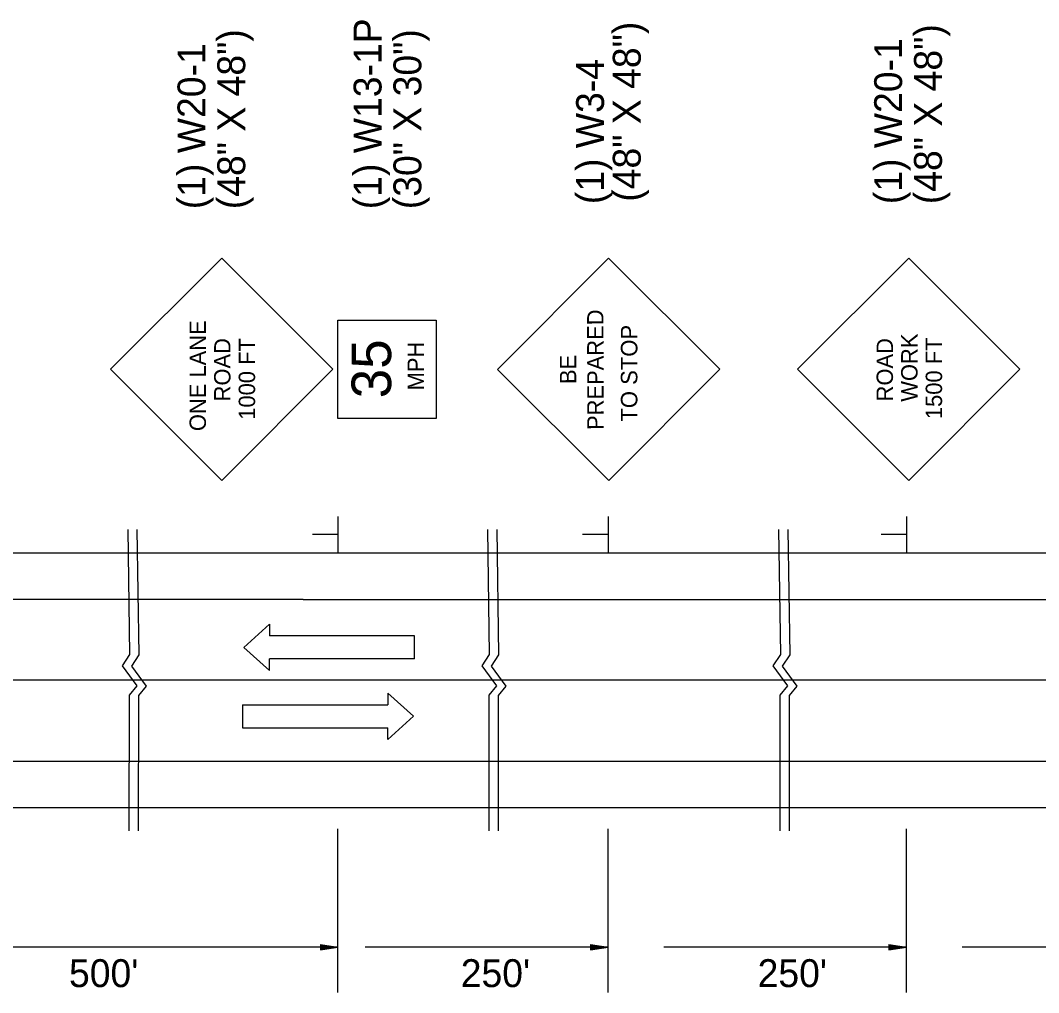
# Model space of a CAD drawing. Extents: x 1678017 to 1687792, y 404433 to 413488.
# Drawn here: x 1679003.11 to 1679025, y 409249.96 to 409270.86 of the extents above; entities that cross this region are included whole.
import ezdxf

# ---------------------------------------------------------------- set-up
doc = ezdxf.new("R2010")
doc.units = 0
doc.layers.add('Default', color=7, linetype='Continuous')
doc.layers.add('S_GRAVEL_ROAD', color=7, linetype='Continuous')

msp = doc.modelspace()

# ---------------------------------------------------------------- linework, layer by layer
at = {"layer": 'Default'}
for p, q in [((1679007.439, 409265.753), (1679005.048, 409263.362)), ((1679007.439, 409265.753), (1679009.827, 409263.362)), ((1679015.755, 409265.753), (1679013.371, 409263.358)), ((1679015.755, 409265.753), (1679018.15, 409263.367)), ((1679022.212, 409265.753), (1679019.822, 409263.362)), ((1679022.212, 409265.753), (1679024.6, 409263.362)), ((1679005.048, 409263.362), (1679007.439, 409260.972)), ((1679009.827, 409263.362), (1679007.439, 409260.972)), ((1679013.371, 409263.358), (1679015.764, 409260.972)), ((1679018.15, 409263.367), (1679015.764, 409260.972)), ((1679019.822, 409263.362), (1679022.212, 409260.972)), ((1679024.6, 409263.362), (1679022.212, 409260.972)), ((1679009.935, 409260.198), (1679009.935, 409259.416)), ((1679015.745, 409260.198), (1679015.745, 409259.416)), ((1679022.161, 409260.198), (1679022.161, 409259.416)), ((1679009.923, 409259.809), (1679009.389, 409259.809)), ((1679015.733, 409259.809), (1679015.199, 409259.809)), ((1679022.149, 409259.809), (1679021.615, 409259.809)), ((1678953.639, 409259.416), (1679044.491, 409259.416)), ((1679009.188, 409258.416), (1678996.885, 409258.416)), ((1679009.188, 409258.416), (1679044.491, 409258.416)), ((1679044.491, 409256.678), (1679000.269, 409256.678)), ((1678997.456, 409254.939), (1679009.188, 409254.939)), ((1679009.188, 409254.939), (1679044.491, 409254.939)), ((1678953.639, 409253.939), (1679044.491, 409253.939)), ((1679009.935, 409249.96), (1679009.935, 409253.481)), ((1679015.745, 409249.96), (1679015.745, 409253.481)), ((1679022.161, 409249.96), (1679022.161, 409253.481)), ((1679009.935, 409250.939), (1679000.861, 409250.939)), ((1679009.56, 409250.996), (1679009.935, 409250.939)), ((1679009.56, 409250.996), (1679009.56, 409250.883)), ((1679009.56, 409250.986), (1679009.872, 409250.939)), ((1679009.56, 409250.977), (1679009.808, 409250.939)), ((1679009.56, 409250.967), (1679009.745, 409250.939)), ((1679009.56, 409250.958), (1679009.682, 409250.939)), ((1679009.56, 409250.948), (1679009.619, 409250.939)), ((1679009.56, 409250.883), (1679009.935, 409250.939)), ((1679009.56, 409250.921), (1679009.682, 409250.939)), ((1679009.56, 409250.902), (1679009.808, 409250.939)), ((1679009.56, 409250.892), (1679009.872, 409250.939)), ((1679009.56, 409250.911), (1679009.745, 409250.939)), ((1679009.56, 409250.931), (1679009.619, 409250.939)), ((1679015.745, 409250.939), (1679010.526, 409250.939)), ((1679015.37, 409250.996), (1679015.745, 409250.939)), ((1679015.37, 409250.996), (1679015.37, 409250.883)), ((1679015.37, 409250.986), (1679015.682, 409250.939)), ((1679015.37, 409250.977), (1679015.618, 409250.939)), ((1679015.37, 409250.967), (1679015.555, 409250.939)), ((1679015.37, 409250.958), (1679015.492, 409250.939)), ((1679015.37, 409250.948), (1679015.429, 409250.939)), ((1679015.37, 409250.883), (1679015.745, 409250.939)), ((1679015.37, 409250.921), (1679015.492, 409250.939)), ((1679015.37, 409250.902), (1679015.618, 409250.939)), ((1679015.37, 409250.892), (1679015.682, 409250.939)), ((1679015.37, 409250.911), (1679015.555, 409250.939)), ((1679015.37, 409250.931), (1679015.429, 409250.939)), ((1679022.161, 409250.939), (1679016.942, 409250.939)), ((1679021.786, 409250.996), (1679022.161, 409250.939)), ((1679021.786, 409250.996), (1679021.786, 409250.883)), ((1679021.786, 409250.986), (1679022.098, 409250.939)), ((1679021.786, 409250.977), (1679022.034, 409250.939)), ((1679021.786, 409250.967), (1679021.971, 409250.939)), ((1679021.786, 409250.958), (1679021.908, 409250.939)), ((1679021.786, 409250.948), (1679021.845, 409250.939)), ((1679021.786, 409250.883), (1679022.161, 409250.939)), ((1679021.786, 409250.921), (1679021.908, 409250.939)), ((1679021.786, 409250.902), (1679022.034, 409250.939)), ((1679021.786, 409250.892), (1679022.098, 409250.939)), ((1679021.786, 409250.911), (1679021.971, 409250.939)), ((1679021.786, 409250.931), (1679021.845, 409250.939)), ((1679028.577, 409250.939), (1679023.358, 409250.939))]:
    msp.add_line(p, q, dxfattribs=at)
msp.add_lwpolyline([(1679009.934, 409262.306), (1679009.934, 409264.419), (1679012.047, 409264.419), (1679012.047, 409262.306)], close=True, dxfattribs=at)
for points in [[(1679005.417, 409259.916), (1679005.457, 409257.229), (1679005.295, 409256.987), (1679005.611, 409256.555), (1679005.445, 409256.355), (1679005.444, 409253.439)], [(1679005.616, 409259.916), (1679005.657, 409257.221), (1679005.495, 409256.979), (1679005.811, 409256.546), (1679005.645, 409256.346), (1679005.644, 409253.439)], [(1679013.151, 409259.916), (1679013.192, 409257.229), (1679013.03, 409256.987), (1679013.346, 409256.555), (1679013.18, 409256.355), (1679013.179, 409253.439)], [(1679013.351, 409259.916), (1679013.392, 409257.221), (1679013.23, 409256.979), (1679013.546, 409256.546), (1679013.379, 409256.346), (1679013.379, 409253.439)], [(1679019.411, 409259.916), (1679019.452, 409257.229), (1679019.29, 409256.987), (1679019.606, 409256.555), (1679019.439, 409256.355), (1679019.439, 409253.439)], [(1679019.611, 409259.916), (1679019.652, 409257.221), (1679019.489, 409256.979), (1679019.806, 409256.546), (1679019.639, 409256.346), (1679019.639, 409253.439)]]:
    msp.add_lwpolyline(points, dxfattribs=at)
at = {"layer": 'S_GRAVEL_ROAD'}
for p, q in [((1679007.914, 409257.384), (1679008.463, 409257.884)), ((1679008.463, 409257.884), (1679008.463, 409257.634)), ((1679011.585, 409257.634), (1679008.463, 409257.634)), ((1679011.585, 409257.134), (1679011.585, 409257.634)), ((1679008.463, 409256.884), (1679007.914, 409257.384)), ((1679011.585, 409257.134), (1679008.463, 409257.134)), ((1679008.463, 409256.884), (1679008.463, 409257.134)), ((1679011.011, 409256.401), (1679011.559, 409255.901)), ((1679011.011, 409256.401), (1679011.011, 409256.151)), ((1679007.888, 409256.151), (1679011.011, 409256.151)), ((1679007.888, 409256.151), (1679007.888, 409255.651)), ((1679011.559, 409255.901), (1679011.011, 409255.401)), ((1679007.888, 409255.651), (1679011.011, 409255.651)), ((1679011.011, 409255.401), (1679011.011, 409255.651))]:
    msp.add_line(p, q, dxfattribs=at)

# ---------------------------------------------------------------- texts
at = {"layer": 'Default'}
for s, height, rotation, p in [('(1) W13-1P', 0.6, 90, (1679010.874, 409266.804)), ('(48" X 48")', 0.6, 90, (1679007.943, 409266.804)), ('(30" X 30")', 0.6, 90, (1679011.73, 409266.804)), ('(48" X 48")', 0.6, 90, (1679016.448, 409266.965)), ('(48" X 48")', 0.6, 90, (1679022.925, 409266.912)), ('(1) W20-1', 0.6, 90, (1679022.069, 409266.912)), ('(1) W20-1', 0.6, 90, (1679007.087, 409266.804)), ('(1) W3-4', 0.6, 90, (1679015.659, 409266.912)), ('PREPARED', 0.3521, 90.1003, (1679015.651, 409262.058)), ('ONE LANE', 0.3521, 90.0004, (1679007.098, 409262.033)), ('TO STOP', 0.3544, 90.0006, (1679016.376, 409262.237)), ('ROAD', 0.352, 90, (1679007.626, 409262.672)), ('1000 FT', 0.3522, 90.0006, (1679008.155, 409262.277)), ('ROAD', 0.3521, 90.0004, (1679021.872, 409262.672)), ('WORK', 0.352, 90, (1679022.4, 409262.665)), ('1500 FT', 0.3522, 90.0006, (1679022.928, 409262.291)), ('35', 0.851, 90, (1679011.081, 409262.739)), ('MPH', 0.3522, 90.0006, (1679011.786, 409262.908)), ('BE', 0.3521, 90.1004, (1679015.062, 409263.046))]:
    msp.add_text(s, height=height, rotation=rotation, dxfattribs=at).set_placement(p)
for s, p in [("500'", (1679004.154, 409250.079)), ("250'", (1679012.578, 409250.079)), ("250'", (1679018.962, 409250.079))]:
    msp.add_text(s, height=0.6, dxfattribs=at).set_placement(p)

doc.saveas('drawing.dxf')
